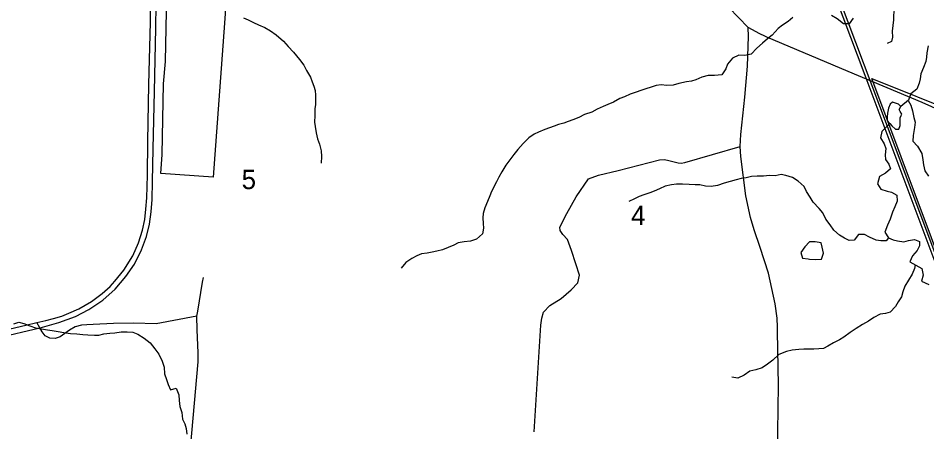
# Model space of a CAD drawing. Extents: x 0 to 34, y 0 to 22.
# Drawn here: x 6.01 to 7.976, y 18.731 to 19.626 of the extents above; entities that cross this region are included whole.
import ezdxf

# ---------------------------------------------------------------- set-up
doc = ezdxf.new("R2010")
doc.units = 0
for name, color, linetype in [('GM_X_City_Street', 7, 'Continuous'), ('GM_X_Corporation', 7, 'Continuous'), ('GM_X_County_Road', 7, 'Continuous'), ('GM_X_Major_River', 7, 'Continuous'), ('GM_X_Minor_Lake', 7, 'Continuous'), ('GM_X_Minor_River', 7, 'Continuous'), ('GM_X_Rail_Line', 7, 'Continuous'), ('GM_X_Section_Text', 7, 'Continuous'), ('GM_X_State_Route', 7, 'Continuous'), ('GM_X_Township_Road', 7, 'Continuous')]:
    doc.layers.add(name, color=color, linetype=linetype)

msp = doc.modelspace()

# ---------------------------------------------------------------- linework, layer by layer
at = {"layer": 'GM_X_City_Street'}
msp.add_lwpolyline([(7.127, 18.7306), (7.1413, 18.9613), (7.1433, 18.9765), (7.1471, 18.9893), (7.1608, 19.0041), (7.1855, 19.0191), (7.2072, 19.0376), (7.2213, 19.0528), (7.2252, 19.0698), (7.217, 19.0945), (7.2076, 19.123), (7.199, 19.1466), (7.1892, 19.158), (7.1828, 19.1664), (7.1821, 19.1736), (7.1974, 19.2031), (7.218, 19.2391), (7.2443, 19.2781), (7.266, 19.2864), (7.3083, 19.2959), (7.3978, 19.3195), (7.4087, 19.3198), (7.4186, 19.3181), (7.4387, 19.3128), (7.445, 19.3121), (7.4531, 19.3135), (7.5725, 19.348)], dxfattribs=at)
at = {"layer": 'GM_X_Corporation'}
for points in [[(7.573, 20.2166), (7.8422, 19.5022), (8.1668, 18.6372)], [(8.1793, 18.6363), (7.8577, 19.4956), (8.0515, 19.417)]]:
    msp.add_lwpolyline(points, dxfattribs=at)
msp.add_lwpolyline([(6.3445, 19.7994), (6.4475, 19.7921), (6.4432, 19.7329), (6.4647, 19.7318), (6.4572, 19.6149), (6.4322, 19.2814), (6.3195, 19.2898), (6.3221, 19.331), (6.3247, 19.4839), (6.3294, 19.5324), (6.3322, 19.6775), (6.3272, 19.7138), (6.3267, 19.7897), (6.3445, 19.7941)], close=True, dxfattribs=at)
at = {"layer": 'GM_X_County_Road'}
for points in [[(7.6532, 18.948), (7.653, 18.9568), (7.6525, 18.9766), (7.6481, 19.0074), (7.6338, 19.0739), (7.6162, 19.1295), (7.603, 19.1676), (7.5951, 19.1943), (7.5849, 19.241), (7.574, 19.3262), (7.5725, 19.348), (7.574, 19.374), (7.5828, 19.4548), (7.5886, 19.5222), (7.5907, 19.586), (7.5902, 19.6059)], [(7.602, 18.2822), (7.6125, 18.3372), (7.6238, 18.442), (7.645, 18.589), (7.649, 18.6371), (7.6503, 18.6497), (7.653, 18.6804), (7.6556, 18.8319), (7.6532, 18.948)]]:
    msp.add_lwpolyline(points, dxfattribs=at)
at = {"layer": 'GM_X_Major_River'}
for points in [[(7.979, 19.5656), (7.9762, 19.5508), (7.9757, 19.5413), (7.9745, 19.5319), (7.9691, 19.519), (7.9637, 19.5054), (7.9617, 19.4944), (7.9601, 19.4849), (7.9551, 19.4721), (7.9421, 19.4619), (7.9367, 19.4483), (7.9199, 19.4344)], [(7.915, 19.4394), (7.9025, 19.444), (7.8972, 19.4395), (7.8937, 19.4312), (7.8917, 19.4202), (7.8905, 19.4119), (7.8908, 19.4043), (7.8965, 19.3978)], [(7.915, 19.4394), (7.9025, 19.444), (7.8972, 19.4395), (7.8937, 19.4312), (7.8917, 19.4202), (7.8905, 19.4119), (7.8908, 19.4043), (7.8965, 19.3978), (7.901, 19.3928), (7.9085, 19.3859), (7.9161, 19.3859), (7.9188, 19.3938), (7.9185, 19.4037), (7.9186, 19.4101), (7.9209, 19.415), (7.9224, 19.4181), (7.9187, 19.4238), (7.9168, 19.428), (7.9199, 19.4344)], [(7.8965, 19.3978), (7.901, 19.3928), (7.9085, 19.3859), (7.9161, 19.3859), (7.9188, 19.3938), (7.9185, 19.4037), (7.9186, 19.4101), (7.9209, 19.415), (7.9224, 19.4181), (7.9187, 19.4238), (7.9168, 19.428), (7.9199, 19.4344)], [(7.9199, 19.4344), (7.915, 19.4394)], [(7.8965, 19.3978), (7.8789, 19.3805), (7.8761, 19.3672), (7.8844, 19.3542), (7.8877, 19.344), (7.8864, 19.3299), (7.8871, 19.3197), (7.8942, 19.3101), (7.8975, 19.2999), (7.8872, 19.2901), (7.8743, 19.2834), (7.87, 19.2671), (7.8771, 19.2556), (7.8903, 19.2517), (7.9001, 19.249), (7.9118, 19.2425), (7.9121, 19.2296), (7.9075, 19.2175), (7.9024, 19.2057), (7.8974, 19.191), (7.8916, 19.1777), (7.8854, 19.1626), (7.8932, 19.1504), (7.9034, 19.1462), (7.9133, 19.1442), (7.9269, 19.1418), (7.9368, 19.1444), (7.9497, 19.1466), (7.9603, 19.1427), (7.9606, 19.1328), (7.9556, 19.123), (7.9452, 19.1117), (7.9394, 19.0984), (7.953, 19.0911), (7.9658, 19.0838), (7.9687, 19.0698), (7.9652, 19.0569), (7.9811, 19.0495)]]:
    msp.add_lwpolyline(points, dxfattribs=at)
at = {"layer": 'GM_X_Minor_Lake'}
for points in [[(7.7478, 19.1399), (7.7346, 19.1418), (7.7228, 19.1419), (7.7122, 19.1313), (7.7035, 19.1188), (7.7076, 19.1063), (7.7194, 19.1047)], [(7.7194, 19.1047), (7.7223, 19.1043), (7.7352, 19.1035), (7.7484, 19.1042), (7.7526, 19.1175), (7.7497, 19.1304), (7.7478, 19.1399)]]:
    msp.add_lwpolyline(points, dxfattribs=at)
at = {"layer": 'GM_X_Minor_River'}
for points in [[(7.8453, 19.7572), (7.8543, 19.7455), (7.8626, 19.733), (7.866, 19.7205), (7.8743, 19.7091), (7.878, 19.6992), (7.8833, 19.6886), (7.8954, 19.6779), (7.901, 19.6657), (7.9062, 19.6532), (7.9058, 19.6437), (7.9043, 19.6324), (7.9046, 19.6225), (7.9027, 19.6096), (7.9011, 19.5975), (7.9022, 19.5846), (7.8999, 19.5751), (7.8905, 19.571)], [(6.4982, 19.6265), (6.5084, 19.6219), (6.5197, 19.6161), (6.5303, 19.6115), (6.5443, 19.6053), (6.5563, 19.5984), (6.5688, 19.5896), (6.5846, 19.5759), (6.5943, 19.5648), (6.606, 19.5526), (6.6195, 19.5366), (6.6285, 19.5244), (6.6341, 19.5126), (6.6427, 19.4981), (6.6468, 19.4882), (6.6505, 19.4787), (6.6527, 19.4692), (6.6541, 19.459), (6.654, 19.4389), (6.6524, 19.4294), (6.652, 19.4154), (6.6519, 19.4009), (6.6529, 19.3915), (6.6555, 19.3778), (6.6584, 19.3649), (6.6625, 19.3535), (6.6658, 19.3387), (6.6665, 19.3265), (6.6664, 19.3121)], [(7.6863, 19.627), (7.6764, 19.6187), (7.6643, 19.6108), (7.6548, 19.6036), (7.6415, 19.5893), (7.6316, 19.581), (7.621, 19.5715), (7.6085, 19.5606), (7.5963, 19.5481), (7.5827, 19.5451), (7.5698, 19.5459), (7.5558, 19.5391), (7.5451, 19.5263), (7.5413, 19.516), (7.5326, 19.5032), (7.5171, 19.5021), (7.5034, 19.5017), (7.4894, 19.4984), (7.4769, 19.4927), (7.4671, 19.4894), (7.4565, 19.4879), (7.4402, 19.4845), (7.4277, 19.4808), (7.414, 19.4804), (7.4016, 19.4812), (7.391, 19.4801), (7.38, 19.4764), (7.3686, 19.4726), (7.358, 19.4692), (7.3478, 19.4655), (7.3349, 19.461), (7.322, 19.4557), (7.3125, 19.452), (7.2985, 19.4437), (7.286, 19.4388), (7.2761, 19.4346), (7.2632, 19.4286), (7.2516, 19.4224)], [(7.8172, 19.6258), (7.8085, 19.6137), (7.7964, 19.6138), (7.7824, 19.6241), (7.7703, 19.6317)], [(7.9363, 19.448), (7.9418, 19.4377), (7.9452, 19.4255), (7.9486, 19.4111), (7.9512, 19.4009), (7.95, 19.3891), (7.9469, 19.3721), (7.9461, 19.3599), (7.9559, 19.3489), (7.9653, 19.3329), (7.9679, 19.3193), (7.9694, 19.3083), (7.972, 19.2958), (7.9803, 19.284)], [(7.2516, 19.4224), (7.2355, 19.4175), (7.2237, 19.4108), (7.2104, 19.4059), (7.2005, 19.4022), (7.1911, 19.3989), (7.1793, 19.3955), (7.1698, 19.3922), (7.1603, 19.3884), (7.1501, 19.3847), (7.1364, 19.3791), (7.1266, 19.3746), (7.1152, 19.3667), (7.1034, 19.3543), (7.0919, 19.3419), (7.0828, 19.3306), (7.0656, 19.3079), (7.0568, 19.2936), (7.0503, 19.2818), (7.0453, 19.2713), (7.0349, 19.2509), (7.0311, 19.241), (7.0257, 19.2293), (7.0199, 19.2157), (7.0168, 19.2032), (7.0156, 19.1937), (7.0167, 19.1812), (7.0173, 19.1717), (7.015, 19.1592), (7.0024, 19.1479), (6.9891, 19.1431), (6.9751, 19.142), (6.9626, 19.1395), (6.9528, 19.1346), (6.941, 19.1297), (6.9285, 19.1245), (6.9164, 19.1219), (6.9061, 19.1193), (6.8955, 19.1175), (6.883, 19.1157), (6.8731, 19.1116), (6.8625, 19.106), (6.8492, 19.0974), (6.8393, 19.0849)], [(7.8932, 19.1504), (7.8882, 19.1443), (7.8769, 19.1436), (7.8667, 19.1452), (7.8523, 19.1521), (7.8417, 19.1578), (7.8285, 19.1574), (7.819, 19.1453), (7.8084, 19.1446), (7.7986, 19.15), (7.7872, 19.1564), (7.7751, 19.1667), (7.7672, 19.1789), (7.7578, 19.1907), (7.7511, 19.2044), (7.7435, 19.2142), (7.7307, 19.2276), (7.7239, 19.2386), (7.7164, 19.2507), (7.7111, 19.2618), (7.6983, 19.2728), (7.6855, 19.2812), (7.6715, 19.285), (7.6616, 19.2873), (7.6484, 19.2847), (7.6363, 19.2855), (7.623, 19.284), (7.6094, 19.2837), (7.5969, 19.2834), (7.5859, 19.2804), (7.5746, 19.2785), (7.5636, 19.2759), (7.5507, 19.2725), (7.5378, 19.2688), (7.5238, 19.2639), (7.5098, 19.2613), (7.4977, 19.2625), (7.4852, 19.2648), (7.475, 19.2652), (7.4625, 19.266), (7.4477, 19.2664), (7.4349, 19.2665), (7.4239, 19.2654), (7.4103, 19.262), (7.3981, 19.2567), (7.3864, 19.2511), (7.3769, 19.2477), (7.364, 19.2436), (7.3542, 19.2402), (7.3443, 19.2345), (7.3318, 19.2293)], [(7.9515, 19.092), (7.9501, 19.0842), (7.9448, 19.0721), (7.9368, 19.0585), (7.9291, 19.046), (7.9242, 19.0335), (7.9215, 19.0225), (7.9143, 19.0119), (7.9089, 19.0021), (7.8968, 18.9896), (7.8869, 18.987), (7.8756, 18.9855), (7.8619, 18.9783), (7.8505, 18.9704), (7.8369, 18.9632), (7.8236, 18.9542), (7.8107, 18.9455), (7.7971, 18.9357), (7.7876, 18.9297), (7.7747, 18.9233), (7.7626, 18.9161), (7.7527, 18.9108), (7.7429, 18.9105), (7.7323, 18.9094), (7.7201, 18.9098), (7.7103, 18.9098), (7.6997, 18.9087), (7.6853, 18.9076), (7.6728, 18.9046), (7.6565, 18.8979), (7.6429, 18.8858), (7.6319, 18.8767), (7.6201, 18.8692), (7.6068, 18.8647), (7.5936, 18.8621), (7.5811, 18.853), (7.5674, 18.847), (7.5542, 18.8489)], [(6.0011, 18.9642), (6.0117, 18.9676), (6.0226, 18.9648), (6.0358, 18.9598), (6.0483, 18.9559), (6.0612, 18.9536), (6.0736, 18.9512), (6.0838, 18.95), (6.0971, 18.948), (6.1095, 18.9453), (6.1239, 18.9437), (6.1375, 18.9424), (6.1504, 18.9416), (6.1613, 18.9408), (6.1753, 18.9395), (6.1852, 18.9399), (6.1958, 18.9424), (6.209, 18.9439), (6.2196, 18.9449), (6.2333, 18.9471), (6.2462, 18.947), (6.2586, 18.9462), (6.2692, 18.9419), (6.2831, 18.9335), (6.2963, 18.9232), (6.3061, 18.9102), (6.3147, 18.8988), (6.3218, 18.8832), (6.3262, 18.8706), (6.3269, 18.8558), (6.3317, 18.8441), (6.3347, 18.8334), (6.3399, 18.8212), (6.352, 18.825), (6.3584, 18.8109), (6.3587, 18.7984), (6.3605, 18.7851), (6.3649, 18.7722), (6.3663, 18.7581), (6.3708, 18.7482), (6.3738, 18.7376), (6.3756, 18.7258)]]:
    msp.add_lwpolyline(points, dxfattribs=at)
at = {"layer": 'GM_X_Rail_Line'}
msp.add_lwpolyline([(8.1892, 18.5986), (8.0513, 18.9649), (7.8912, 19.3911), (7.7899, 19.661)], dxfattribs=at)
at = {"layer": 'GM_X_State_Route'}
msp.add_line((5.8346, 18.9042), (6.0574, 18.9556), dxfattribs=at)
for points in [[(5.8362, 18.917), (6.0272, 18.9618), (6.051, 18.9673), (6.0705, 18.9719), (6.0867, 18.9761), (6.1046, 18.9812), (6.1203, 18.9873), (6.1417, 18.9969), (6.1689, 19.0124), (6.1924, 19.03), (6.2093, 19.0452), (6.2198, 19.0567), (6.2394, 19.0808), (6.2587, 19.1117), (6.2708, 19.1398), (6.2792, 19.1668), (6.2843, 19.1903), (6.287, 19.2128), (6.2886, 19.237), (6.2901, 19.2864), (6.2912, 19.3592), (6.2935, 19.4826), (6.2965, 19.6173), (6.2983, 19.722)], [(6.0574, 18.9556), (6.0582, 18.9558), (6.0984, 18.9669), (6.1344, 18.9804), (6.1637, 18.9953), (6.1936, 19.0153), (6.2203, 19.0394), (6.2434, 19.0671), (6.2621, 19.0935), (6.2775, 19.1245), (6.2879, 19.1536), (6.2947, 19.1801), (6.2983, 19.2065), (6.3004, 19.2337), (6.3012, 19.272), (6.3027, 19.3432), (6.3052, 19.4673), (6.3081, 19.6043), (6.3098, 19.7089), (6.3101, 19.7218)], [(7.6259, 19.587), (7.6153, 19.5921), (7.5902, 19.6059), (7.5479, 19.6486), (7.5424, 19.6552)], [(8.0984, 19.3837), (8.0083, 19.4248), (7.966, 19.443), (7.8065, 19.5105), (7.6304, 19.5849), (7.6259, 19.587)]]:
    msp.add_lwpolyline(points, dxfattribs=at)
at = {"layer": 'GM_X_Township_Road'}
for points in [[(6.3971, 18.9809), (6.3989, 18.9914), (6.4094, 19.0543), (6.4112, 19.0648)], [(6.3373, 18.1755), (6.3996, 18.8819), (6.4002, 18.889), (6.3997, 18.9018), (6.3981, 18.9517), (6.3971, 18.9809), (6.3087, 18.9643), (6.2604, 18.966), (6.2164, 18.9652), (6.1731, 18.9631), (6.1589, 18.9621)], [(6.1589, 18.9621), (6.1478, 18.9613), (6.1338, 18.9577), (6.1219, 18.9507), (6.1017, 18.9364), (6.0904, 18.9323), (6.0787, 18.9335), (6.069, 18.9381), (6.0622, 18.9468), (6.0574, 18.9556), (6.051, 18.9673)]]:
    msp.add_lwpolyline(points, dxfattribs=at)

# ---------------------------------------------------------------- texts
at = {"layer": 'GM_X_Section_Text'}
for s, p in [('5', (6.494, 19.2559)), ('4', (7.3365, 19.1782))]:
    msp.add_text(s, height=0.0419, rotation=0, dxfattribs=at).set_placement(p)

doc.saveas('drawing.dxf')
